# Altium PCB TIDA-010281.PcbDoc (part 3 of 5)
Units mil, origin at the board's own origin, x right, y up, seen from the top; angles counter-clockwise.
Board outline 3455.86 x 1121.8 mil, 8 copper layers (Top Layer, GND1, Sig1, PWR1, PWR2, Sig2, GND2, Bottom Layer), stack 59.155 mil thick; 291 components, 180 nets, 941 pads, 539 vias.
Unrouted connection lines stored in the file: 41.
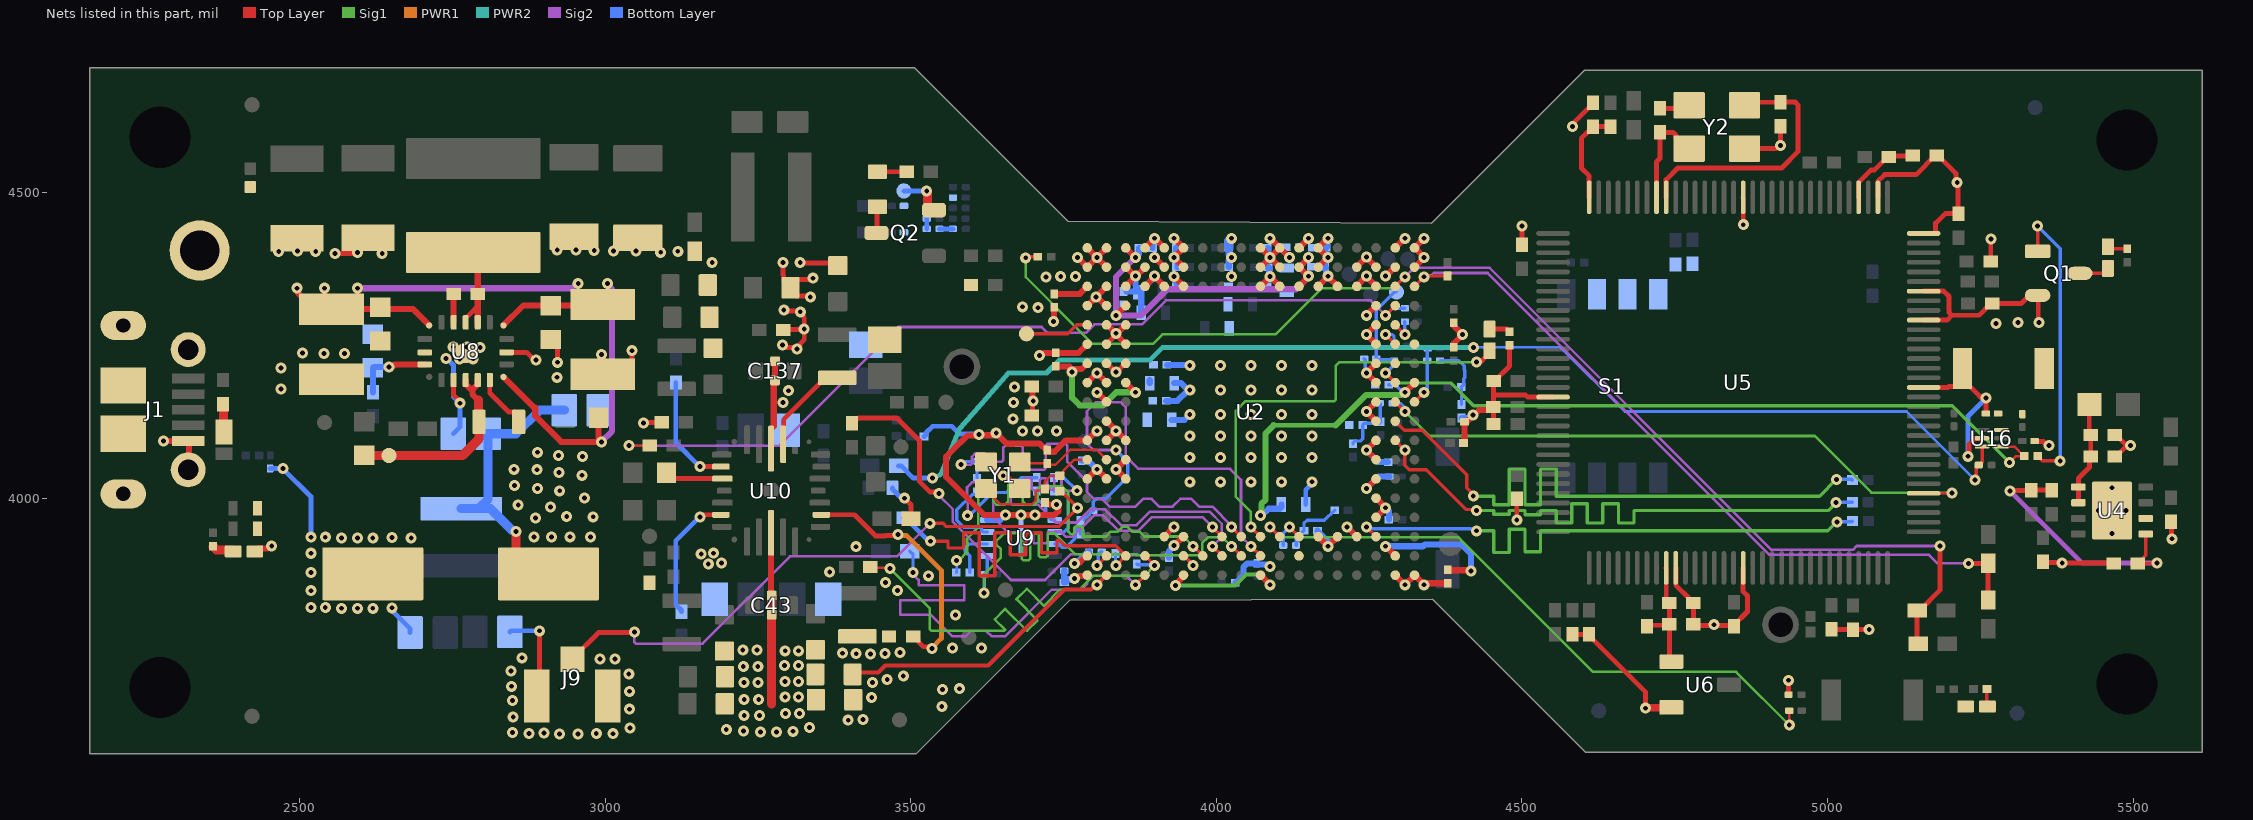
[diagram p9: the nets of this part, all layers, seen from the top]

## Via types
v1: diameter 18, hole 8, Top Layer to Bottom Layer, tented both sides, 533 vias
v2: diameter 19.68, hole 7.87, Top Layer to Bottom Layer, 5 vias
v3: diameter 17, hole 8, Top Layer to Bottom Layer, tented both sides, 1 vias

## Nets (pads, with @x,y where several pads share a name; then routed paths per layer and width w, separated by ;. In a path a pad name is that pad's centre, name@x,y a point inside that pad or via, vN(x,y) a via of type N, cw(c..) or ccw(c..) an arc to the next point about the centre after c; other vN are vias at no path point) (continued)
AR_1V8: C54.2 C55.1 C56.1 C57.1 C58.1 C59.1 C60.1 C61.1 C62.1 C63.1 C64.1 C65.1 C66.1 C67.1 C68.1 C77.2 L7.2 R121.2 U2.A12 U2.B1 U2.C11 U2.C15 U2.C18 U2.F1 U2.K1 U2.M16 U2.M17 U2.M18 U2.U2 U2.V11 | length 2277.4
  Top Layer w7: C54.2@3404.97,3711.44 3408.06,3714.53 3446.79,3714.53 3458.14,3725.89 3626.77,3725.89 3751.24,3850.36 3794.91,3850.36 3802.69,3858.15 v1@3804.51,3858.15 ; C77.2@3405.84,3670.07 C77.2@3406.45,3669.46 ; v1(3804.62,3858.15) v1@3804.51,3858.15 ; U2.B1@3820.26,3873.89 v1@3804.51,3858.15
  Top Layer w10: C63.1@3737.19,4215.47 3759.7,4215.47 3759.7,4212.67 3764,4208.36 v1(3764,4206.2) ; v1@3764,4211.16 3779.58,4211.16 U2.A12@3788.76,4220.35 ; v1(3835.75,4298.83) U2.C15@3851.76,4314.84 ; U2.C11@3851.76,4188.85 v1(3867.5,4173.11) ; U2.C18@3851.76,4409.33 v1(3867.5,4393.58) ; v1(3933.28,3857.12) 3934.81,3858.65 3934.81,3860.9 3946.24,3872.34 U2.F1@3946.24,3873.89 ; U2.K1@4072.23,3873.89 v1(4087.98,3858.15) ; U2.M16@4135.22,4346.33 4135.22,4346.77 4150.97,4362.51 v1(4150.97,4362.94) ; U2.M18@4135.22,4409.33 v1(4150.97,4425.07) ; v1@4150.97,4362.08 U2.M17@4135.22,4377.83 v1(4150.97,4393.58) ; v1(4276.95,3921.14) U2.U2@4292.7,3905.39 ; v1(4308.45,4173.11) U2.V11@4324.2,4188.85 ; C60.1@4378.33,3882.68 4379.19,3881.82 4415.97,3881.82 v1(4416.83,3880.96)
  Sig1 w7: v1(3933.28,3857.12) 4030.72,3857.12 4048.7,3875.1 4071.02,3875.1 v1(4087.98,3858.15)
  Sig1 w8: 4093.73,4119.09 4195.17,4119.09
  Sig1 w10: v1(3764,4206.2) 3764,4163.79 3776.3,4151.49 3814.59,4151.49 3836.2,4173.11 v1(3867.5,4173.11) ; v1(4072.24,3971.63) 4073.78,3973.16 4073.78,3990.32 4080.1,3996.65 4080.1,4105.46 4093.73,4119.09 ; 4195.17,4119.09 4244.54,4168.46 4303.81,4168.46 v1(4308.45,4173.11)
  Sig2 w10: v1@3835.69,4297.67 3836.86,4298.83 3876.84,4298.83 3919.6,4341.59 4130.47,4341.59 4150.97,4362.08 v1(4150.97,4362.94) ; v1(3835.75,4298.83) 3835.75,4361.82 v1(3867.5,4393.58)
  Bottom Layer w5.5: C61.1@4282,4185.3 4292.87,4185.3 4305.07,4173.11 v1(4308.45,4173.11)
  Bottom Layer w10: v1(3867.5,4393.58) 3873.35,4399.42 C68.1@3873.35,4409.24 ; C65.1@3891,4188 C65.1@3891,4192.68 ; v1(4072.24,3971.63) 4074.41,3971.63 4085.36,3982.57 4103.74,3982.57 4106.24,3985.07 C59.1@4106.24,3989.57 ; v1(4276.95,3921.14) 4338.22,3921.14 4341.28,3924.2 4400.39,3924.2 4416.83,3907.76 v1(4416.83,3880.96)
  other v1: 3397.65,3636.55 3421.77,3637.6 3436.12,3673.98 3437.45,3698.29 3461.48,3703.42 3487.69,3708.55 3410.75,3745.31 3434.22,3745.02 3388.24,3746.16 3457.58,3745.69 3482.37,3747.02 3738.48,4109.58
AR_CS1: R9.2 R91.1 U2.C2 | length 735.4
  Top Layer w5.5: v1(3532.57,3929.37) 3560.83,3929.37 3560.83,3918.26 3586.33,3918.26 3586.33,3943.43 3611.83,3943.43 3611.83,3872.77 3637.33,3872.77 3637.33,3943.43 3662.83,3943.43 3662.83,3907.17 3688.33,3907.17 3688.33,3943.43 3713.83,3943.43 3713.83,3910.66 3739.33,3910.66 3739.33,3931.28 3742.55,3931.28 3751.83,3922 3835.15,3922 3849.01,3908.14 U2.C2@3851.76,3905.39 v1(3836.01,3889.64)
  Bottom Layer w5.5: R9.2@3835,3909.17 3835,3890.65 v1(3836.01,3889.64)
  Bottom Layer w8: R91.1@3488.75,3967.81 3490.72,3967.81 3526.77,3931.76 3530.18,3931.76 v1(3532.57,3929.37)
AR_GPIO_0: U2.M2
AR_GPIO_1: R129.2 U2.L3 | length 1033
  Top Layer w4.2: v1(4937.34,3628.68) 4937.39,3628.74 4937.39,3652.02 R129.2@4937.45,3652.08
  Top Layer w5.5: v1(4087.98,3952.63) U2.L3@4103.72,3936.89
  Sig1 w4.2: v1@4091.71,3952.63 v1(4087.98,3952.63) 4104.87,3935.74 4395.79,3935.74 4616.05,3715.47 4850.55,3715.47 v1(4937.34,3628.68)
AR_GPIO_2: LD3.1 U2.K3 | length 713.6
  Top Layer w5.5: v1(4056.48,3952.63) U2.K3@4072.23,3936.89
  Top Layer w8: v1(4425.64,4222.47) 4427.55,4224.38 4434.38,4224.38 4447.13,4237.13 LD3.1@4447.13,4241.07
  Sig1 w4.2: v1(4056.48,3952.63) 4056.48,3977.37 4031.74,4002.11 4031.74,4142.65 4047.18,4158.09 4192.72,4158.09 4195.18,4160.55 4195.18,4216.27 4201.38,4222.47 v1(4425.64,4222.47)
AR_HOSTINTR1: R3.1 U2.B2 | length 48.9
  Top Layer w5.5: v1(3804.51,3889.64) U2.B2@3820.26,3905.39
  Bottom Layer w5.5: v1(3804.51,3889.64) 3806.9,3892.03 3806.9,3906.61 3808.61,3908.31 3808.61,3909.61 3811.22,3912.22 R3.1@3812.51,3912.22
AR_MCUCLKOUT: U2.V13
AR_MISO1: R139.1 U2.D1 | length 768.2
  Top Layer w5.5: v1(3867.5,3858.15) U2.D1@3883.25,3873.89
  Sig2 w4.2: v1(3503.64,3878.26) 3503.64,3875.22 3512.94,3865.92 3512.94,3857.27 3587.52,3857.27 3587.52,3833.07 3482.61,3833.07 3482.61,3808.87 3532.82,3808.87 3534.92,3806.77 3567.99,3773.7 3589.51,3773.7 3598.68,3782.86 3623.39,3782.86 3632.55,3773.7 3654.07,3773.7 3730.65,3850.27 3779.06,3850.27 3788.76,3859.97 3788.76,3863.04 3798.46,3872.75 3852.9,3872.75 v1(3867.5,3858.15)
  Bottom Layer w5.5: R139.1@3498.24,3913.28 3503.64,3907.88 v1(3503.64,3878.26)
AR_MOSI1: R136.2 U2.F2 | length 773.8
  Top Layer w5.5: U2.F2@3946.24,3905.39 3947.09,3905.39 3961.99,3890.49 v1(3961.99,3889.64)
  Top Layer w8: R136.2@3403.94,4122.66 3403.94,4124.63 3409.78,4130.48 3413.78,4130.48 3414.47,4131.16 3476.56,4131.16 3514.37,4093.35 3514.37,4026.92 3531.61,4009.68 3544.25,4009.68 v1(3546.16,4007.77)
  Sig2 w4.2: v1(3546.16,4007.77) 3546.16,4004.42 3568.88,3981.71 3568.88,3960.92 3663.87,3865.92 3719.69,3865.92 3761.57,3907.8 3853.13,3907.8 3854.15,3906.77 3945.71,3906.77 3961.99,3890.49 v1(3961.99,3889.64)
AR_NERR_OUT: R21.1 R94.1 U2.U15 | length 1446.5
  Top Layer w4.2: v1(3039.16,4085.79) 3072.59,4085.79 R94.1@3072.69,4085.88
  Top Layer w5.5: v1(4276.95,4299.09) U2.U15@4292.7,4314.84
  Sig2 w4.2: v1(3039.16,4085.79) 3285.02,4085.79 3479.14,4279.9 3714.18,4279.9 3723.76,4270.31 3786.58,4270.31 3800.5,4284.23 3878.22,4284.23 3917.54,4323.55 4252.49,4323.55 v1(4276.95,4299.09)
  Bottom Layer w5.5: v1(4276.95,4299.09) 4288.62,4310.76 R21.1@4308.45,4310.76
AR_NERRIN: R22.1 U2.U14 | length 43.4
  Top Layer w5.5: U2.U14@4292.7,4283.34 v1(4308.45,4267.59)
  Bottom Layer w5.5: v1(4308.45,4267.59) R22.1@4308.45,4288.76
AR_NRST: C130.1 R59.1 R108.1 TP14.1 U2.U11 U16.4 | length 1353.6
  Top Layer w4.2: U16.4@5284.42,4084.09 5305.57,4084.09 R108.1@5320.98,4068.68 ; v1(5297.5,4058.31) 5298.02,4058.31 5308.38,4068.68 R108.1@5321.77,4068.68
  Top Layer w5.5: v1(4276.95,4204.6) U2.U11@4292.7,4188.85
  Sig1 w5.5: v1(4276.95,4204.6) 4293.2,4188.36 4383.59,4188.36 4420.7,4151.25 5204.3,4151.25 5297.23,4058.31 v1(5297.5,4058.31)
  Bottom Layer w5.5: v1(4276.95,4204.6) 4289.15,4216.8 4289.15,4224.04 4286.81,4226.38 4263.32,4226.38 C130.1@4261.7,4228 4261.3,4228.4 4261.3,4307.3 4291.1,4337.1 TP14.1@4294.6,4337.1
AR_NRST_2: C120.1 R124.1 SW2.1 U16.6
AR_NRST_PMIC: R95.1 R178.2 U16.3 | length 2030.1
  Top Layer w5.5: v1(5241.09,4029.84) 5243.48,4032.23 5243.48,4051.48 5246.09,4054.09 R178.2@5247.38,4054.09 5248.68,4054.09 5252.92,4058.33 U16.3@5252.92,4084.09
  PWR2 w8: v1@3535.23,4032.51 v1(3535.48,4032.61) 3548.12,4037.85 3549.31,4039.03 3550.58,4042.11 3580.42,4114.08 3580.68,4114.72 3581.12,4115.23 ; 3581.16,4115.27 3659.92,4204.66 3722.02,4204.66 3743.11,4225.76 3891.12,4225.76 3912,4246.64 v1(4420.77,4246.64)
  Bottom Layer w4.2: v1(4420.77,4246.64) 4563.37,4246.64 4668.4,4141.61 5129.32,4141.61 v1(5241.09,4029.84)
  Bottom Layer w8: R95.1@3480.19,4052.72 3484.13,4052.72 3504.23,4032.61 v1(3535.48,4032.61)
AR_OSC_CLKOUT: TP17.1 U2.A14 | length 105.5
  Top Layer w5.5: TP17.1@3689.3,4268.85 3756.96,4268.85 3771.45,4283.34 U2.A14@3788.76,4283.34
AR_PMIC_CLKOUT_SOP2: R85.1 R103.1 U2.V10 | length 96.6
  Top Layer w5.5: U2.V10@4324.2,4157.36 v1(4339.94,4173.11)
  Bottom Layer w5.5: v1(4339.94,4173.11) 4344.93,4178.09 R85.1@4344.93,4224.99 4344.93,4244.41 R103.1@4345.62,4245.1
AR_QSPI_CLK: R47.1 U2.H2 | length 760.7
  Top Layer w5.5: v1(3993.49,3921.14) U2.H2@4009.24,3905.39
  Sig2 w4.2: v1(3772.05,4012.05) 3750.13,4012.05 3746.55,4015.63 3746.55,4029.87 3744.09,4032.33 3737.42,4032.33 3734.96,4029.87 3734.96,4016.39 3732.5,4013.93 3729.02,4013.93 3723.42,4019.53 3723.42,4029.87 3720.96,4032.33 3714.18,4032.33 3711.36,4029.52 3711.36,4015.63 3708.59,4012.85 3700.3,4012.85 3697.84,4015.31 3697.84,4029.87 3695.38,4032.33 3687.98,4032.33 3685.52,4029.87 3685.52,4015.31 3683.06,4012.85 3678.7,4012.85 3676.24,4015.31 3676.24,4027.38 3673.78,4029.84 3667.82,4029.84 3663.86,4025.88 3663.86,3991.69 3666.33,3989.23 3708.08,3989.23 3737.31,3960 3771.94,3960 3793.6,3981.66 3817.72,3981.66 3843.6,3955.77 3869.39,3955.77 3891.32,3977.7 3989.07,3977.7 4008.79,3957.98 4008.79,3936.82 4008.98,3936.63 v1(3993.49,3921.14)
  Bottom Layer w5.5: R47.1@3734.37,4033.51 3750.59,4033.51 v1(3772.05,4012.05)
AR_QSPI_CLK_T: R47.2 U9.6 | length 102.2
  Bottom Layer w5.5: R47.2@3734.37,4011.47 3747.4,4011.47 3757.25,4001.62 3757.25,3950.78 3750.99,3944.52 U9.6@3735.4,3944.52
AR_QSPI_CS: R43.1 U2.J2 U9.1 | length 770.9
  Top Layer w5.5: v1(4024.98,3921.14) U2.J2@4040.73,3905.39
  Sig1 w4.2: v1(3619.9,3844.47) 3619.9,3875.21 3647.47,3902.79 3647.47,3916.63 3639.73,3924.37 3639.73,3929.34 3647.76,3937.38 3652.78,3942.4 3652.87,3942.4 3667.07,3942.4 3678.43,3942.4 3681.27,3939.56 3681.27,3900.87 3684.11,3898.03 3692.63,3898.03 3695.47,3900.87 3695.47,3939.56 3698.31,3942.4 3706.83,3942.4 3709.67,3939.56 3709.67,3905.77 3712.51,3902.93 3721.03,3902.93 3723.87,3905.77 3723.87,3939.56 3726.71,3942.4 3730.97,3942.4 3735.14,3942.4 3769.74,3907.8 3869.64,3907.8 3870.91,3906.54 3970.81,3906.54 3976.59,3912.32 3976.59,3926.37 3985.96,3935.74 4010.38,3935.74 v1(4024.98,3921.14)
  Bottom Layer w5.5: v1(3619.9,3844.47) 3620.04,3844.61 3620.04,3873.99 3624.09,3878.04 3624.09,3880.18 3625.17,3881.26 U9.1@3625.17,3905.15
AR_QSPI_D0: R6.1 U2.H3 | length 745.1
  Top Layer w5.5: v1(3993.49,3952.63) U2.H3@4009.24,3936.89
  Sig2 w4.2: v1(3593.03,3971.08) 3593.03,3997.08 3592.02,3998.09 3592.02,4017.53 3600.13,4025.64 3615.59,4025.64 3635.24,4005.99 3635.24,3967.78 3659.02,3944 3697.84,3944 3700.3,3941.54 3700.3,3928.47 3702.76,3926.01 3721.3,3926.01 3723.76,3928.47 3723.76,3942.64 3726.22,3945.1 3745.36,3945.1 3753.84,3936.63 3764.21,3936.63 3799.43,3971.85 3814.73,3971.85 3839.99,3946.58 3872.3,3946.58 3894.55,3968.83 3977.29,3968.83 v1(3993.49,3952.63)
  Bottom Layer w5.5: v1(3593.03,3971.08) 3595.33,3971.08 3633.25,4009 3656,4009 3680.51,4033.51 R6.1@3706.27,4033.51
AR_QSPI_D0_T: R6.2 U9.5 | length 62.4
  Bottom Layer w5.5: R6.2@3706.27,4011.47 3706.27,3999.75 3720.96,3985.06 3720.96,3973.39 3730.15,3964.2 U9.5@3735.4,3964.2
AR_QSPI_D1: R46.1 U2.G2 | length 750.6
  Top Layer w5.5: v1(3961.99,3921.14) U2.G2@3977.74,3905.39
  Sig1 w4.2: v1(3575.01,3898.14) 3578.74,3898.14 3592,3911.39 3592,3933.42 3610.05,3951.47 3610.05,4005.15 3624.12,4019.22 3630.16,4019.22 3635,4014.38 3635,3994.04 3639.84,3989.2 3654.36,3989.2 3659.2,3994.04 3659.2,4019.22 3659.2,4021.32 3664.04,4026.16 3678.56,4026.16 3683.4,4021.32 3683.4,4019.22 3683.4,3994.04 3688.24,3989.2 3702.76,3989.2 3707.6,3994.04 3707.6,4014.38 3712.44,4019.22 3719.7,4019.22 3747.78,4019.22 3757.72,4009.29 3757.72,3944.96 3761.68,3941 3765.15,3941 3767.62,3943.46 3767.62,3951.66 3770.08,3954.12 3778.7,3954.12 3781.16,3951.66 3781.16,3937.16 3819.13,3937.16 3826.93,3944.97 3838.83,3944.97 3846.75,3952.89 3854.7,3952.89 3862.62,3944.97 3874.51,3944.97 3882.32,3937.16 3945.97,3937.16 v1(3961.99,3921.14)
  Bottom Layer w4.2: R46.1@3574.6,3878.26 3575.01,3878.67 v1(3575.01,3898.14)
AR_QSPI_D1_T: R46.2 U9.2 | length 83.1
  Bottom Layer w5.5: R46.2@3596.64,3878.26 3596.64,3905.95 3593.42,3909.17 3592.42,3909.17 3589.2,3912.4 3589.2,3919.54 3594.49,3924.83 U9.2@3625.17,3924.83
AR_QSPI_D2: R44.1 R48.1 U2.J3 | length 744.4
  Top Layer w5.5: v1(4024.98,3952.63) U2.J3@4040.73,3936.89
  Sig2 w4.2: v1(3582.3,4054.72) 3582.8,4054.22 3597.67,4054.22 3600.13,4056.68 3600.13,4067.62 3606.02,4073.51 3619.64,4073.51 3633.55,4059.59 3648.9,4059.59 3651.36,4062.05 3651.36,4082.68 3654.68,4086 3680.37,4086 3683.06,4083.31 3683.06,4049.04 3685.52,4046.58 3718.5,4046.58 3720.96,4049.04 3720.96,4086.38 3723.42,4088.84 3752.99,4088.84 3755.83,4086 3755.83,4059.59 3788.32,4027.1 3788.32,4010.18 3799.77,3998.73 3812.87,3998.73 3825.5,3986.1 3867.51,3986.1 3880.14,3998.73 3893.84,3998.73 3906.47,3986.1 3928.24,3986.1 3940.87,3998.73 3959.14,3998.73 3971.77,3986.1 3993.54,3986.1 4024.98,3954.65 v1(4024.98,3952.63)
  Bottom Layer w5.5: v1(3582.3,4054.72) 3585.68,4054.72 3590.81,4059.85 R44.1@3608.37,4059.85 ; R48.1@3608.37,4032.12 R44.1@3608.37,4059.85 ; R44.1@3608.85,4059.85 R44.1@3608.37,4059.85
AR_QSPI_D2_T: R48.2 U9.3 | length 121.9
  Bottom Layer w5.5: R48.2@3608.37,4010.07 3608.37,4009.28 3604.82,4005.73 3600.39,4005.73 3575.38,3980.72 3575.38,3963.77 3586.62,3952.53 3612.88,3952.53 3616.11,3949.31 3616.11,3946.69 3618.28,3944.52 U9.3@3625.17,3944.52
AR_QSPI_D3: R45.1 R49.1 U2.K2 | length 763.2
  Top Layer w5.5: v1(4056.48,3921.14) U2.K2@4072.23,3905.39
  Sig2 w4.2: v1(3836.01,4078.62) 3798.6,4078.62 3788.37,4088.84 3788.37,4142.05 3803.23,4156.91 3843.24,4156.91 3851.54,4148.61 3851.54,4069 3872.83,4047.7 4022.42,4047.7 4040.28,4029.84 4040.28,3937.33 v1(4056.48,3921.14)
  Bottom Layer w4.2: R49.1@3782.81,3963.66 3782.81,3964.44 3787.01,3968.64 3787.79,3968.64 3794.14,3974.99 3794.14,3975.65 3797.41,3978.91 R45.1@3798.7,3978.91
  Bottom Layer w5.5: R45.1@3798.7,3978.91 3798.7,3993.8 3803.85,3998.95 3819.33,3998.95 3855.08,4034.7 3855.08,4059.54 v1(3836.01,4078.62)
AR_QSPI_D3_T: R49.2 U9.7 | length 71.2
  Bottom Layer w5.5: U9.7@3735.4,3924.83 3742.29,3924.83 3744.46,3922.66 3744.46,3922.04 3746.97,3919.54 3754.14,3919.54 3764.67,3930.07 3765.07,3930.07 3768.4,3933.39 3768.4,3945.8 3771.62,3949.03 3776.18,3949.03 3776.18,3945.49 3777.55,3944.11 R49.2@3777.55,3941.21
AR_RS232RX: R5.2 R30.2 R63.1 U2.V16 | length 1246.3
  Top Layer w5.5: U2.V16@4324.2,4346.33 v1(4339.94,4362.08) 4341.11,4363.24 R5.2@4378.13,4363.24
  Top Layer w8: v1(5230.62,3893.11) 5262.54,3893.11 R63.1@5262.71,3893.28 R30.2@5262.71,3833.28
  Sig1 w4.2: v1(4339.94,4362.08) v1@4343.11,4362.08
  Sig2 w4.2: v1(4339.94,4362.08) 4342.59,4364.72 4352.28,4364.72 4355.84,4368.28 4443.77,4368.28 4905.07,3906.98 5166.19,3906.98 5180.07,3893.11 v1(5230.62,3893.11)
AR_RS232TX: R4.2 R38.2 R51.1 U2.U16 | length 2038.2
  Top Layer w5.5: v1@3688.09,4394.61 R4.2@3707.72,4394.61 R4.2@3707.9,4394.43 ; U2.U16@4292.7,4346.33 v1(4308.45,4362.08)
  Top Layer w8: R38.2@5148.39,3761.87 5146.6,3763.66 R51.1@5146.6,3816.05 5150.54,3816.05 5184.16,3849.68 v1(5184.16,3921.54)
  Sig1 w4.2: v1(3688.09,4393.11) 3688.09,4361.33 3796.59,4252.83 3896.89,4252.83 3911.84,4267.77 4097,4267.77 4172.61,4343.38 4289.75,4343.38 v1(4308.45,4362.08)
  Sig2 w4.2: v1(4308.45,4362.08) 4323.05,4376.68 4447.25,4376.68 4908.55,3915.38 5041.41,3915.38 5047.57,3921.54 v1(5184.16,3921.54)
AR_SOP0: R83.2 R158.2 R159.1 R174.2 | length 105.5
  Bottom Layer w5.5: R159.1@4223.5,4089.12 4223.5,4089.91 4227.05,4093.46 4236,4093.46 4239.22,4096.68 R158.2@4239.22,4119.6 4241.84,4122.21 4266.49,4122.21 R174.2@4269.1,4124.82 4268.19,4125.73 4268.19,4154.39 R83.2@4267.28,4155.3
AR_SOP1: R84.2 R170.2 R171.1 | length 100.6
  Bottom Layer w5.5: R84.2@4130.41,3922.4 4130.41,3933.54 R170.2@4143.32,3946.46 4143.32,3958.65 4148.32,3963.64 4176.89,3963.64 R171.1@4193.42,3980.18
AR_SOP2: R85.2 R172.2 R176.2 | length 109.7
  Bottom Layer w5.5: R85.2@4365.96,4224.99 4396.89,4224.99 4405.74,4216.14 4405.74,4209.91 4406.2,4209.44 4406.2,4196.48 4404.96,4195.24 4404.96,4185.35 4401.41,4181.8 R176.2@4400.62,4181.8 4401.11,4181.32 R172.2@4401.11,4153.05
AR_SPICLK1: R75.2 R134.2 U2.D2 | length 780.8
  Top Layer w4.2: R134.2@3435.11,3886.26 v1@3464.75,3886.26
  Top Layer w5.5: U2.D2@3883.25,3905.39 v1(3899,3889.64)
  Top Layer w8: R134.2@3433.89,3887.48 R134.2@3435.11,3886.26 ; v1@3464.75,3886.26 v1(3465.97,3885.04)
  Sig1 w4.2: v1(3465.97,3885.04) 3531.37,3819.64 3531.37,3785.32 3533.83,3782.86 3649.46,3782.86 3652.43,3782.86 3654.17,3784.6 3637.38,3801.39 3654.5,3818.5 3690.1,3782.9 3707.21,3800.01 3672.69,3834.53 3689.8,3851.65 3717.83,3823.61 3744.5,3850.27 3775.99,3850.27 3798.46,3872.75 3882.1,3872.75 v1(3899,3889.64)
  Bottom Layer w5.5: R75.2@3869.6,3892.2 3870.88,3890.92 3897.72,3890.92 v1(3899,3889.64)
AR_SYNC_IN: U2.U12
AR_SYNC_OUT_SOP1: R84.1 U2.M3 | length 56.7
  Top Layer w5.5: v1(4119.47,3952.63) U2.M3@4135.22,3936.89
  Bottom Layer w5.5: R84.1@4109.37,3922.4 4109.37,3942.53 v1(4119.47,3952.63)
AR_TCK: R66.2 U2.T3 | length 971.9
  Top Layer w5.5: v1(4245.46,3952.63) U2.T3@4261.2,3936.89
  Sig1 w5.5: v1(4425.64,3946.46) 4453.89,3946.46 4453.89,3910.92 4479.39,3910.92 4479.39,3949.1 4504.89,3949.1 4504.89,3912.07 4530.39,3912.07 4530.39,3946.46 4720.7,3946.46 5000.64,3946.46 v1(5015.19,3961.01)
  Bottom Layer w5.5: v1(4245.46,3952.63) 4247.85,3950.24 4254.61,3950.24 4254.93,3949.93 4416.17,3949.93 4417.24,3948.85 4423.25,3948.85 v1(4425.64,3946.46) ; v1(5015.19,3961.01) 5039.65,3961.01 R66.2@5040.83,3962.19
AR_TDI: R69.2 U2.U9 | length 1057.3
  Top Layer w5.5: U2.U9@4292.7,4125.86 4307.77,4110.79 4336.9,4110.79 4409.76,4037.94 4409.76,4017.04 4420.37,4006.43 v1(4420.37,4003.26)
  Sig1 w5.5: v1(4420.37,4003.26) 4420.62,4003 4425.64,4003 4453.89,4003 4453.89,3989.3 4479.39,3989.3 4479.39,4047.46 4504.89,4047.46 4504.89,3989.3 4530.39,3989.3 4530.39,4047.46 4555.89,4047.46 4555.89,4003 4582.9,4003 4986.91,4003 v1(5014.42,4030.51)
  Bottom Layer w5.5: v1(5014.42,4030.51) 5039.41,4030.51 R69.2@5040.49,4029.42
AR_TDO_SOP0: R83.1 U2.U10 U5.37 | length 1048.9
  Top Layer w4.2: U5.37@5157.18,4007.77 5157.33,4007.91 5203.63,4007.91 v1(5203.78,4008.06)
  Top Layer w5.5: U2.U10@4292.7,4157.36 v1(4308.45,4141.61)
  Sig1 w4.2: v1(4308.45,4141.61) 4348.46,4101.59 4979.27,4101.59 5071.83,4009.04 v1@5203.78,4009.04
  Bottom Layer w4.2: R83.1@4288.32,4155.3 4301.27,4155.3 4308.45,4148.13 v1(4308.45,4141.61)
AR_TMS: R67.2 U2.U8 | length 1007.7
  Top Layer w5.5: U2.U8@4292.7,4094.37 v1(4308.45,4078.62) 4308.45,4053.32 4315.63,4046.14 4343.65,4046.14 4408.39,3981.4 4423.84,3981.4 v1(4425.64,3979.6)
  Sig1 w5.5: v1(4425.64,3979.6) 4453.89,3979.6 4453.89,3973.78 4479.39,3973.78 4479.39,3979.6 4504.89,3979.6 4504.89,3972.55 4530.39,3972.55 4530.39,3979.6 4555.89,3979.6 4555.89,3959.2 4581.39,3959.2 4581.39,3990.56 4606.89,3990.56 4606.89,3959.2 4632.39,3959.2 4632.39,3990.56 4657.89,3990.56 4657.89,3959.2 4683.39,3959.2 4683.39,3979.6 4692.04,3979.6 5000.74,3979.6 v1(5014.06,3992.92)
  Bottom Layer w5.5: v1(5014.06,3992.92) 5040.28,3992.92 R67.2@5040.51,3993.15
AR_VBGAP: C69.1 U2.A16 | length 59.2
  Top Layer w10: C69.1@3734.67,4334 3776.43,4334 U2.A16@3788.76,4346.33
AR_WARMRST: R23.1 U2.U13 | length 52.5
  Top Layer w5.5: v1(4276.95,4267.59) U2.U13@4292.7,4251.85
  Bottom Layer w5.5: v1(4276.95,4267.59) 4287.51,4267.59 4290.72,4264.38 R23.1@4290.72,4249.29
AR_XTAL_N: C71.2 U2.B7 Y1.3 | length 159.9
  Top Layer w4: Y1.3@3678.09,4056.69 3720.4,4056.69 3722.86,4054.22 3736.32,4054.22 3760.84,4078.74 3804.39,4078.74 U2.B7@3820.26,4062.87
AR_XTAL_P: C14.2 R109.1 U2.A7 Y1.1 | length 226
  Top Layer w4: Y1.1@3621.87,4014.49 3646.72,3989.63 3697.93,3989.63 3704.65,3996.36 3704.65,4009.85 3707.19,4012.38 3719.34,4012.38 3719.34,4027.12 3728.93,4036.7 3744.81,4036.7 3749.7,4041.59 3749.7,4044.95 3767.62,4062.87 U2.A7@3788.76,4062.87
BOOTN: R80.2 R96.1 | length 21.7
  Bottom Layer w8: R96.1@3547.14,4440.29 R80.2@3568.85,4440.29
BUCK_VCC: C116.1 R113.1 TP4.1 U8.4 U8.5 | length 324.4
  Top Layer w10: U8.4@2771.82,4193.15 2771.82,4186.26 2782.68,4175.39 ; U8.5@2791.5,4193.15 2791.5,4186.26 2782.68,4177.44 2782.68,4175.39 ; 2792.55,4160.23 2782.68,4170.1 2782.68,4175.39
  Top Layer w15: R113.1@2605.99,4069.91 2606.24,4069.66 TP4.1@2646.13,4069.66 2766.6,4069.66 2793.47,4096.54 C116.1@2793.47,4124.7 ; C116.1@2792.55,4125.63 2792.55,4160.23
BUCK_VIN: C119.2 C122.1 C123.1 C124.1 C125.1 C128.2 C129.2 L1.2 R114.1 U8.7 U8.11 U8.17 | length 1864
  Top Layer w10: v1(2495.65,4343.33) 2497.18,4341.8 2497.18,4335.86 2524.3,4308.74 C124.1@2551.86,4308.74 ; v1(2540.97,4343.33) 2540.97,4319.63 C124.1@2551.86,4308.74 ; v1(2595,4343.33) 2595,4329.33 C124.1@2575.04,4309.37 ; U8.17@2712.02,4282.47 2685.12,4309.37 C124.1@2575.04,4309.37 ; U8.7@2833.58,4198.31 2884.19,4147.7 2885.63,4147.7 2885.63,4134.42 2928.11,4091.95 v1(2993.92,4091.95) 2993.92,4094.11 2989.22,4098.81 R114.1@2989.22,4131.16 ; U8.11@2833.58,4282.47 2866.36,4315.25 2994.67,4315.25 C125.1@2996.02,4316.6 ; C124.1@2551.86,4308.74 2574.41,4308.74 C124.1@2575.04,4309.37
  Top Layer w15: v1(2853.96,3945.1) 2853.96,3915.37 2893.26,3876.06 C129.2@2907.19,3876.06
  Sig2 w10: v1(2595,4343.33) 2946.13,4343.33 2953.68,4350.88 v1(2955.85,4350.88) ; v1(2993.92,4091.95) 3011.42,4109.45 3011.42,4341.57 3003.96,4349.03 v1(3003.96,4351.19)
  Bottom Layer w15: L1.2@2764.49,3982.86 L1.2@2793.24,3982.86 ; v1(2853.96,3945.1) 2852.04,3947.02 2847.97,3947.02 2812.13,3982.86 L1.2@2793.24,3982.86 ; C119.2@2933.08,4143.96 2892.72,4143.96 2853.96,4105.2 C128.2@2808.53,4105.2 2808.53,3998.15 L1.2@2793.24,3982.86
  other v1: 2883.35,3936.38 2911.89,3936.37 2975.99,3936.1 2942.2,3936.64 2885.91,3967.5 2980.4,3969.36 2937.07,3969.59 2910.79,3985.51 2857.71,3988.39 2965.92,4000.1 2925.6,4011.91 2889.29,4015.81 2851.64,4020.34 2961.8,4037.31 2924.27,4041.98 2888.4,4046.33 2850.93,4047.11 2963.03,4068.05 2923.93,4069.39 2889.07,4074.95
CLKSEL0: R82.2
FB_B1: R121.1 U10.3 | length 410.8
  Top Layer w8: U10.3@3353.74,3972.67 3407.88,3972.67 3442.33,3938.22 3458.28,3938.22 3458.5,3938.44 3477.21,3938.44 v1(3479.12,3940.35) ; R121.1@3503.72,3773.64 3505.69,3773.64 3511.53,3767.79 3511.53,3765.82 3520.68,3756.67 3529.17,3756.67 3532.22,3753.62 v1(3534.93,3753.62)
  PWR1 w8: v1(3479.12,3940.35) 3481.03,3938.44 3493.32,3938.44 3550.12,3881.64 3550.12,3770.39 3534.93,3755.2 v1(3534.93,3753.62)
FB_B2: R126.1 U10.21 | length 211.4
  Top Layer w8: v1(3155.05,3968.73) 3157.76,3968.73 3161.7,3972.67 U10.21@3189.37,3972.67
  Bottom Layer w8: R126.1@3124.79,3814.26 3124.79,3816.23 3115.49,3825.53 3115.49,3930.4 3153.81,3968.73 v1(3155.05,3968.73)
FB_B3: R128.1 U10.17 | length 188.4
  Top Layer w8: v1(3154.97,4051.38) U10.17@3189.37,4051.41
  Bottom Layer w8: R128.1@3115.49,4189.05 3115.49,4090.87 v1(3154.97,4051.38)
GND: C1.1 C4.2 C5.2 C6.2 C7.1 C8.1 C9.2 C10.1 C11.2 C12.2 C13.1 C14.1 C16.1 C17.1 C18.1 C19.1 C20.2 C21.2 C22.1 C23.1 C24.1 C25.1 C26.1 C27.1 C28.1 C29.1 C35.1 C36.2 C37.2 C38.2 C39.2 C40.2 C41.2 C42.2 C43.2 C54.1 C55.2 C56.2 C57.2 C58.2 C59.2 C60.2 C61.2 C62.2 C63.2 C64.2 C65.2 C66.2 C67.2 C68.2 C69.2 C70.2 C71.1 C72.1 C73.2 C74.2 C75.2 C76.2 C77.1 C78.2 C79.2 C80.2 C81.2 C82.2 C83.2 C84.2 C85.2 C86.1 C87.2 C88.2 C89.2 C90.2 C91.2 C92.2 C93.1 C94.2 C95.2 C96.2 C97.2 C98.2 C99.1 C100.2 C101.2 C102.2 C103.2 C104.1 C105.1 C106.2 C107.2 C116.2 C118.1 C119.1 C120.2 C122.2 C123.2 C124.2 C125.2 C127.1 C128.1 C129.1 C130.2 C131.2 C132.1 C133.1 C134.1 C135.2 C136.2 C137.2 J1.5 J1.6 J1.7 J1.8 J1.9 J1.10 J1.11 J9.2@3004.32,3676.11 J9.3@2888.18,3676.11 LD1.2 LD2.2 NT1.2 NT2.2 NT3.2 NT4.1 Q1.2 Q2.2 R3.2 R24.1 R27.1 R29.1 R42.2 R65.1 R72.2 R73.2 R90.1 R93.2 R96.2 R97.1 R98.2 R112.1 R119.1 R122.2 R125.1 R131.1 R141.2 R158.1 R170.1 R172.1 S1.6 S1.7 S1.8 SW2.2 TP15.1 TP20.1 U2.A1 U2.A2 U2.A6 U2.A8 U2.A11 U2.A13 U2.A15 U2.A17 U2.A18 U2.B6 U2.B8 U2.B9 U2.B10 U2.B11 U2.B12 U2.B13 U2.B14 U2.B15 U2.B16 U2.B17 U2.B18 U2.C6 U2.C7 U2.C8 U2.C12 U2.C13 U2.C14 U2.C16 U2.C17 U2.D16 U2.D17 U2.D18 U2.E3 U2.E16 U2.E17 U2.E18 U2.F3 U2.F16 U2.F17 U2.F18 U2.K16 U2.K17 U2.K18 U2.L16 U2.L17 U2.L18 U2.N3 U2.N16 U2.N17 U2.N18 U2.P3 U2.P16 U2.R3 U2.R16 U2.R17 U2.T4 U2.T5 U2.T6 U2.T7 U2.T8 U2.T9 U2.T10 U2.T11 U2.T12 U2.T13 U2.T14 U2.T15 U2.T16 U2.T17 U2.U1 U2.U17 U2.U18 U2.V1 U2.V17 U2.V18 U4.6 U4.9@5465.42,3979.58 U5.10 U5.17 U5.48 U5.55 U5.58 U5.64 U5.66 U5.80 U5.114 U6.2 U8.3 U8.6 U8.9 U8.19 U8.21 U9.4 U9.9 U10.12 U10.26 U16.2 Y1.2 Y1.4 Y2.2 Y2.4 | length 8245.1
  Top Layer w8: v1(2558.23,4400.16) 2558.31,4400.24 v1@2593.3,4400.24 ; v1(2595,4401.99) 2595,4408.91 C131.2@2611.98,4425.89 ; U8.3@2752.13,4193.15 2752.13,4168.15 2762.37,4157.91 v1(2762.37,4155.21) ; U8.6@2811.19,4193.15 2811.19,4171.95 2842.62,4140.51 2851.48,4140.51 2858.43,4133.56 C116.2@2858.43,4124.7 ; U8.9@2838.75,4238.42 2871.71,4238.42 2884.4,4225.74 v1(2887.11,4225.74) ; J9.3@2888.18,3676.11 2892.72,3680.64 v1(2892.72,3782.86) ; C122.2@2910.99,4259.46 2922,4248.45 v1(2922,4222.13) ; C125.2@2996.02,4202.43 3023.58,4202.43 3043.92,4222.77 v1(3043.92,4241.04) ; v1(3062.58,4122.88) 3063.15,4123.45 3091.8,4123.45 R122.2@3092.37,4124.03 ; v1(3290.29,4250.59) 3292.99,4250.59 3297.51,4246.07 3311.79,4246.07 v1(3313.71,4244.16) ; C37.2@3291.24,4274.8 3292.2,4275.76 3324.73,4275.76 v1(3325.69,4276.72) ; v1(3291.24,4385.51) 3291.24,4364.51 3292.11,4363.64 3292.11,4355.08 C27.1@3302.88,4344.32 ; v1(3292.16,4307.72) 3293.61,4306.27 3317.71,4306.27 v1(3319.16,4304.82) 3319.16,4302.12 3325.69,4295.58 v1(3325.69,4276.72) ; v1@3312.24,4245.62 3316.45,4249.83 3319.16,4249.83 3319.16,4252.54 3325.69,4259.07 v1(3325.69,4276.72) ; v1(3319.15,4385.52) 3320.14,4384.53 3376.46,4384.53 C105.1@3380.58,4380.41 ; v1(3335.53,4329.19) 3333.87,4330.86 3313.64,4330.86 3302.88,4341.62 C27.1@3302.88,4344.32 ; v1(3339.74,4359.69) 3337.96,4357.9 3313.64,4357.9 3302.88,4347.14 C27.1@3302.88,4344.32 ; v1(3489.9,3999.72) 3500.3,3989.32 R141.2@3500.3,3966.37 ; C89.2@3697.82,4135.45 3699.06,4136.69 3699.06,4157.52 v1(3700.3,4158.76) ; U2.B16@3819.62,4346.33 U2.B16@3820.26,4346.33 ; U2.B12@3820.26,4220.35 3820.97,4220.35 3835.33,4205.99 v1(3836.04,4205.99) 3836.72,4205.99 3851.08,4220.35 U2.C12@3851.76,4220.35 ; U2.B13@3820.26,4251.85 v1@3836.01,4267.59 ; C17.1@4453.44,4120.8 4453.37,4120.87 4453.37,4148.84 C18.1@4453.3,4148.91 4453.51,4149.11 4453.51,4170.36 ; R42.2@4479.55,4250.1 4479.55,4215.67 4455.69,4191.81 C12.2@4453.72,4191.81 4453.51,4191.6 4453.51,4170.36 ; v1(4491.53,3964.35) C10.1@4491.53,3998.9 ; C9.2@4499.97,4414.78 v1(4499.97,4444.91) ; U5.114@4550.88,4165.25 4509.3,4165.25 4506.05,4168.5 4455.37,4168.5 4453.51,4170.36 ; C16.1@4582.9,3776.98 R29.1@4609.94,3776.98 4609.94,3775.01 4701.87,3683.08 v1(4701.87,3656.11) ; v1(4582.9,4608.2) 4584.81,4610.11 4584.81,4613.78 4616.07,4645.04 C21.2@4616.07,4647.01 ; C23.1@4725.84,4637.64 4768.53,4637.64 Y2.2@4773.53,4642.64 ; U5.10@4751.67,3885.72 U5.10@4751.67,3885.72 4751.73,3857.51 4772.78,3836.47 4772.78,3834.5 4778.62,3828.66 C25.1@4780.59,3828.66 C26.1@4780.59,3793.56 4782.39,3791.77 4846.42,3791.77 4869.01,3814.36 4869.01,3839.88 4861.91,3846.99 U5.17@4861.91,3885.72 ; U5.80@4861.91,4492.02 4861.97,4491.96 4861.97,4447.31 v1(4862.09,4447.19) ; Y2.4@4864.08,4571.77 4915.42,4571.77 4920.35,4576.7 v1(4923.05,4576.7) C24.1@4923.05,4608.2 ; R125.1@4936.23,3678.43 v1(4936.22,3701.86) ; C11.2@5006.67,3785.02 5006.76,3784.93 5041.69,3784.93 C7.1@5041.78,3784.84 5041.89,3784.96 5068.03,3784.96 v1(5068.15,3785.07) ; U5.66@5082.38,4492.02 5082.38,4518.04 5093.46,4529.13 5144.91,4529.13 5176.45,4560.66 C22.1@5178.42,4560.66 5180.38,4560.66 5210.26,4530.78 5210.26,4518.13 v1(5212.18,4516.21) 5213.27,4515.12 5213.27,4466.59 R72.2@5214.37,4465.5 5192.52,4465.5 5176.8,4449.78 5176.8,4433.03 5176.74,4432.97 U5.64@5157.18,4432.97 ; U5.48@5157.18,4181 5196.74,4181 5198.23,4182.49 5209.08,4182.49 SW2.2@5220.82,4194.23 ; U5.55@5157.18,4291.23 5195.62,4291.23 5203.48,4299.09 ; U5.58@5157.18,4338.48 5190.04,4338.48 5198.79,4329.73 5198.79,4303.78 5203.48,4299.09 ; SW2.2@5220.82,4211.95 SW2.2@5220.82,4194.23 ; v1(5229.76,4068.4) 5231.67,4070.31 5231.67,4088.16 5240.73,4097.22 5252.26,4097.22 U16.2@5252.92,4097.87 ; C120.2@5259.13,4138.45 v1(5259.14,4163.53) ; v1(5259.14,4163.53) 5257.23,4165.44 5249.62,4165.44 SW2.2@5220.82,4194.23 ; R73.2@5266.71,4387.04 5266.93,4387.27 5266.93,4423.93 v1(5267.16,4424.16) ; C72.1@5338.68,4093.48 5339.85,4092.31 5353.17,4092.31 5359.48,4086 v1(5362.18,4086) ; v1(5345.91,4287.08) 5344.78,4288.2 5344.78,4330.56 Q1.2@5343.65,4331.68 5329.92,4331.68 5316.57,4318.34 R90.1@5269.13,4318.34 5267.16,4318.34 5247.91,4299.09 5203.48,4299.09 ; C13.1@5352.54,3895.84 5353.54,3894.83 5382.9,3894.83 v1(5383.9,3893.83) 5384.18,3893.56 5468.09,3893.56 R27.1@5468.37,3893.28 ; C6.2@5469.63,4103.44 5471.6,4103.44 v1@5487.05,4087.99 ; C5.2@5469.95,4068.12 5471.92,4068.12 5487.96,4084.16 5493.68,4084.16 v1(5495.59,4086.08) ; R24.1@5562.22,3961.39 5562.91,3960.7 5562.91,3934.05 v1(5563.61,3933.36)
  Top Layer w10: v1(2277.16,4093.48) 2277.22,4093.42 2319.31,4093.42 2319.37,4093.35 J1.10@2319.37,4046.11 ; LD1.2@2426.74,3912.62 2431.59,3917.46 2447.81,3917.46 2452.21,3921.86 v1(2454.37,3921.86) ; U10.26@3271.56,3943.14 3271.56,3841.57 C43.2@3272.57,3840.56 ; U10.12@3271.56,4080.94 3271.56,4113.26 3275.79,4117.5 3275.79,4190.32 C137.2@3277.88,4192.41 C137.2@3277.88,4223.9 ; Y1.4@3623.17,4054.18 3630.08,4054.18 3646.39,4037.87 3650.02,4037.87 v3(3651.36,4036.53) ; v3@3649.9,4034.08 3651.01,4035.19 3656.94,4035.19 3672.19,4019.94 Y1.2@3672.19,4013.38 ; C90.2@3697.69,4182.85 3698.99,4181.54 3698.99,4160.07 v1(3700.3,4158.76) ; v1(3710.74,4233.04) 3712.91,4233.04 3717.38,4237.51 3774.43,4237.51 U2.A13@3788.76,4251.85 ; C14.1@3724.34,3990.34 3725.45,3989.23 v1(3738.48,3989.23) 3741.28,3989.23 3741.28,3978.28 3735.46,3972.46 v1(3703.21,3972.46) v1(3680.37,3972.46) v1(3655,3972.46) 3619.79,3972.46 3557.61,4034.64 3557.61,4067.72 3582.02,4092.12 3582.59,4092.12 3592.99,4102.51 3610.06,4102.51 3612.18,4104.63 3614.01,4102.8 3634.43,4102.8 3637.95,4106.32 v1(3639.78,4106.32) 3657.3,4088.8 3668.8,4088.8 3669,4089 3710.92,4089 3722.86,4077.06 3722.86,4076.27 3723.31,4075.82 3735.12,4075.82 3753.66,4094.37 U2.A8@3788.76,4094.37 v1(3804.51,4110.11) ; v1(3733.48,4289.01) 3734.08,4289.6 3734.08,4311.36 C69.2@3734.67,4311.95 ; v1(3767.6,3868.71) 3769.77,3868.71 3773.85,3872.79 3787.66,3872.79 U2.A1@3788.76,3873.89 ; v1(3767.62,3893.2) 3769.15,3894.73 3776.55,3894.73 3787.21,3905.39 U2.A2@3788.76,3905.39 ; v1(3773.02,4393.58) U2.A17@3788.76,4377.83 v1(3804.51,4393.58) ; U2.A6@3788.76,4031.37 v1(3804.51,4047.12) U2.B6@3820.26,4031.37 ; U2.A11@3788.76,4188.85 v1(3804.51,4204.6) U2.B11@3820.26,4188.85 ; U2.A15@3788.76,4314.84 3789.05,4314.84 3803.06,4328.84 v1(3803.35,4328.84) ; U2.A18@3788.76,4409.33 v1(3804.51,4393.58) ; v1@3803.1,4329.14 3804.5,4329.14 3818.81,4314.84 U2.B15@3820.26,4314.84 ; v1@3803.36,4329.14 3819.62,4345.4 U2.B16@3819.62,4346.33 ; v1(3804.51,4173.11) U2.B10@3820.26,4157.36 ; U2.B8@3820.26,4094.37 v1(3836.01,4110.11) ; U2.B9@3820.26,4125.86 v1(3836.01,4110.11) ; U2.B14@3820.26,4283.34 3821.28,4283.34 3834.99,4269.63 v1(3836.01,4269.63) ; U2.B17@3820.26,4377.83 v1(3804.51,4393.58) ; U2.B18@3820.26,4409.33 v1(3804.51,4393.58) ; U2.C6@3851.76,4031.37 v1(3836.01,4047.12) U2.C7@3851.76,4062.87 ; U2.C8@3851.76,4094.37 v1(3836.01,4110.11) ; U2.C13@3851.76,4251.85 3836.01,4267.59 U2.C14@3851.76,4283.34 ; U2.C16@3851.76,4346.33 3867.5,4362.08 U2.D17@3883.25,4377.83 ; U2.C17@3851.76,4377.83 3852.26,4377.83 3867,4363.08 v1(3867.5,4363.08) ; U2.D16@3883.25,4346.33 3883.25,4346.83 3899,4362.58 v1(3899,4363.08) ; U2.D18@3883.25,4409.33 v1(3899,4425.07) U2.E18@3914.75,4409.33 ; v1@3899,4362.08 U2.E16@3914.75,4346.33 ; v1(3899,4393.58) U2.E17@3914.75,4377.83 ; U2.E3@3914.75,3936.89 v1(3930.5,3952.63) ; v1(3930.5,3922.56) 3931.21,3922.56 3945.53,3936.89 U2.F3@3946.24,3936.89 ; v1(3930.5,4362.62) 3930.5,4362.35 3946.24,4346.6 U2.F16@3946.24,4346.33 ; v1(3930.5,4425.07) U2.F18@3946.24,4409.33 v1(3930.5,4393.58) U2.F17@3946.24,4377.83 ; U2.K16@4072.23,4346.33 4072.23,4346.52 4087.98,4362.27 v1(4087.98,4362.45) ; U2.K17@4072.23,4377.83 v1(4087.98,4393.58) ; U2.K18@4072.23,4409.33 v1(4087.98,4393.58) ; v1@4087.98,4362.08 U2.L16@4103.72,4346.33 ; v1(4087.98,4425.07) U2.L18@4103.72,4409.33 ; U2.L17@4103.72,4377.83 v1(4087.98,4393.58) ; v1(4119.47,4393.58) U2.L18@4103.72,4409.33 ; U2.N3@4166.72,3936.89 v1(4182.46,3921.14) U2.P3@4198.21,3936.89 ; U2.N16@4166.72,4346.33 4166.72,4346.77 4182.46,4362.51 v1(4182.46,4362.94) ; U2.N17@4166.72,4377.83 v1(4182.46,4393.58) U2.N18@4166.72,4409.33 v1(4182.46,4425.07) ; v1@4182.46,4362.08 U2.P16@4198.21,4346.33 ; v1(4213.96,3952.63) U2.R3@4229.71,3936.89 ; U2.R16@4229.71,4346.33 4229.71,4346.83 4245.46,4362.58 v1(4245.46,4363.08) ; U2.R17@4229.71,4377.83 4229.71,4378.23 4245.46,4393.98 v1(4245.46,4394.38) ; v1(4245.46,4015.63) U2.T6@4261.2,4031.37 ; v1(4245.46,4299.09) U2.T15@4261.2,4314.84 ; v1@4245.46,4362.08 U2.T16@4261.2,4346.33 ; v1@4245.46,4393.58 U2.T17@4261.2,4377.83 ; U2.T4@4261.2,3968.38 v1(4276.95,3984.13) U2.T5@4261.2,3999.88 ; U2.T7@4261.2,4062.87 v1(4245.46,4078.62) U2.T8@4261.2,4094.37 ; U2.T9@4261.2,4125.86 v1(4245.46,4141.61) U2.T10@4261.2,4157.36 ; U2.T11@4261.2,4188.85 v1(4245.46,4204.6) U2.T12@4261.2,4220.35 ; U2.T13@4261.2,4251.85 v1(4245.46,4267.59) U2.T14@4261.2,4283.34 ; v1(4276.95,4363.08) 4277.45,4363.08 4292.2,4377.83 U2.U17@4292.7,4377.83 ; U2.U1@4292.7,3873.89 v1(4308.45,3858.15) U2.V1@4324.2,3873.89 v1(4339.94,3858.15) 4342.43,3860.63 C60.2@4378.33,3860.63 ; U2.U18@4292.7,4409.33 v1(4308.45,4425.07) ; U2.V17@4324.2,4377.83 v1(4339.94,4393.58) U2.V18@4324.2,4409.33 v1(4339.94,4425.07) ; C96.2@4388.37,4246.78 4388.37,4252.87 v1(4402.94,4267.44) 4388.37,4282.01 C98.2@4388.37,4286.73 ; C102.2@4405.36,4090.24 4405.93,4090.82 C88.2@4405.93,4124.76 4409.76,4124.76 v1@4420.4,4135.4 ; v1(4419.8,4136) 4421.96,4136 4430.03,4144.07 4448.46,4144.07 C18.1@4453.3,4148.91 ; v1(4087.98,4393.58) U2.L18@4103.72,4409.33
  Top Layer w12: v1(4701.87,3656.11) 4702.55,3656.8 4743.74,3656.8 U6.2@4744.43,3657.48
  Top Layer w15: 3272.37,3663.53 3272.37,3808.87 C43.2@3272.57,3809.07 C43.2@3272.57,3840.56 ; v1(3526.1,4502.59) 3527.26,4501.43 3527.26,4478.76 3534.93,4471.1 Q2.2@3538.2,4471.1
  Bottom Layer w5.5: v1(3930.5,4362.62) 3932.47,4360.65 3932.47,4349.93 3932.68,4349.72 3932.89,4349.72 C74.2@3936.37,4346.23 ; C130.2@4241.68,4228 4243.57,4226.11 4243.57,4206.49 v1(4245.46,4204.6) 4257.65,4192.4 4257.65,4187.6 C61.2@4259.95,4185.3
  Bottom Layer w8: R65.1@2451.72,4048.48 2451.83,4048.37 2472.61,4048.37 v1(2472.73,4048.25) 2518.43,4002.55 v1(2518.43,3935.91) ; v1(2651.06,3820.45) 2652.97,3818.54 2652.97,3813.87 2680.91,3785.94 C118.1@2680.91,3780 ; v1@2740.71,4228.58 2751.54,4217.75 2751.54,4166.04 v1(2762.37,4155.21) 2762.37,4116.18 C128.1@2751.38,4105.2 ; C127.1@2844.07,3780.99 2845.95,3782.86 v1(2892.72,3782.86) ; R97.1@3470.06,4016.69 3470.06,4014.72 3483.16,4001.63 3487.99,4001.63 v1(3489.9,3999.72) ; TP15.1@3488.75,4502.59 v1(3526.1,4502.59) R98.2@3526.1,4474.39 R93.2@3526.1,4457.3 R96.2@3526.1,4440.29 ; R119.1@3521.57,4100.58 3522.36,4100.58 3524.66,4102.88 3524.66,4106.45 3535.73,4117.52 3567.16,4117.52 3580.13,4104.55 3611.09,4104.55 v1(3611.59,4104.04) ; C59.2@4146.24,3989.57 4146.24,4013.66 4156.48,4023.9 v1(4156.48,4026.61) ; v1(5229.76,4068.4) 5229.76,4134.14 v1(5259.14,4163.53)
  Bottom Layer w10: U9.4@3625.17,3964.2 3646.74,3964.2 v1(3655,3972.46) ; C101.2@3751.01,3881.17 3751.01,3861.79 C100.2@3751.11,3861.69 3753.05,3861.69 3758.54,3867.18 3766.07,3867.18 v1(3767.6,3868.71) ; v1(3767.62,3893.2) 3769.15,3894.73 3772.69,3894.73 3789.82,3911.86 3791.12,3911.86 R3.2@3791.48,3912.22 ; C97.2@3779.79,4061.22 3790.41,4061.22 v1(3804.51,4047.12) ; C67.2@3853,4338.02 3874.98,4338.02 3877,4336 C73.2@3877,4303 ; v1(3867.5,4363.08) 3867.5,4347.58 3876,4339.08 3899,4362.08 v1(3899,4363.08) ; C68.2@3895.39,4409.24 3895.39,4421.47 v1(3899,4425.07) ; C64.2@3918.02,4159 3936,4159 3953.61,4176.61 3942.22,4188 C65.2@3931,4188 ; C66.2@3919.05,4218 3955.09,4218 v1(3956.48,4216.61) ; C95.2@3922.37,3902.78 3922.37,3913.01 3930.5,3921.14 v1(3930.5,3922.56) ; C62.2@3927,4128 3947.87,4128 v1(3956.48,4136.61) ; C75.2@3934.43,4409.11 3934.35,4409.02 3934.35,4397.43 v1(3930.5,4393.58) 3936.37,4387.7 C76.2@3936.37,4377.73 ; C84.2@4020.26,4377.83 4020.26,4388.85 v1(4024.98,4393.58) 4020.26,4398.3 C85.2@4020.26,4409.33 ; C87.2@4031,3861.38 4031.79,3861.38 4044.6,3874.19 4044.6,3887.25 4050.46,3893.11 C92.2@4065.74,3893.11 4065.74,3891.31 4065.91,3891.14 4082.89,3891.14 4085.81,3888.21 v1(4087.98,3888.21) ; C80.2@4083.77,4377.76 4085.14,4377.76 4086.45,4376.45 4086.45,4363.98 v1(4087.98,4362.45) ; C81.2@4084.39,4409.24 4084.39,4397.16 v1(4087.98,4393.58) ; R170.1@4165.37,3946.46 4182.46,3929.37 v1(4182.46,3921.14) ; C57.2@4177.74,4409.33 4177.74,4398.3 v1(4182.46,4393.58) 4177.39,4388.51 C56.2@4177.39,4378.24 4178.18,4378.24 4179.48,4376.94 4179.48,4368.09 4182.46,4365.11 v1(4182.46,4362.94) ; C57.2@4179.44,4409.4 4179.66,4409.4 4180.95,4410.7 v1@4180.95,4423.56 ; v1(4245.46,4015.63) 4265,4035.17 C91.2@4282.98,4035.17 ; v1@4245.46,4079.47 v1(4245.46,4078.62) 4265.27,4058.8 C103.2@4280.95,4058.8 ; v1(4276.95,3984.13) 4282.16,3978.92 C94.2@4282.16,3964.68 ; R172.1@4401.11,4131.01 4413.91,4131.01 v1@4421,4138.1 ; v1@4421,4136 v1@4421,4138.1 ; v1@4422.04,4139.14 v1@4421,4138.1
  Bottom Layer w15: C85.2@4020.26,4409.33 4020.26,4420.35 v1(4024.98,4425.07)
  other v1: 2925.05,3614.04 2955.47,3613.89 3012.76,3614.46 2875.44,3615.03 2985.47,3614.89 2899.61,3615.6 2848.57,3616.59 3254.23,3617.46 3280.46,3617.21 3307.45,3618.46 3226.5,3618.84 3198.12,3621.63 3040.48,3623.7 3334.16,3624.8 2849.57,3641.9 3227.5,3644.47 3252.26,3644.3 3318.15,3647.37 3294.76,3647.71 3040.06,3654.55 3550.68,3659.15 2848.57,3668.48 3227.5,3670.42 3251.23,3670.24 3294.59,3674.68 3316.27,3674.51 3039.92,3683.84 3551.8,3686.76 3579.59,3688.06 2846.87,3692.08 3226.82,3698.24 3250.21,3698.24 3294.25,3700.12 3316.27,3700.12 3038.64,3711.84 2846.15,3717.1 3225.97,3724.7 3249.7,3724.7 3293.23,3726.23 3316.27,3726.06 2991.44,3736.86 3016.03,3736.72 2863.92,3738.71 3294.59,3750.13 3316.44,3750.13 3225.11,3751.5 3248.67,3751.16 3615.65,3754.48 3567.99,3754.67 4813.98,3792.76 3572.9,3808.68 2568.65,3819.69 2594.93,3819.69 2619.79,3819.69 2518.43,3820.87 2542.05,3820.87 2518.43,3848.42 3478.49,3848.89 3458.47,3861.6 3529.02,3872.82 2518.43,3878.21 3367.38,3879.29 3168.63,3891.88 3190.62,3893.93 3157.12,3908.63 2518.43,3909.71 3176.95,3909.77 3410.21,3920.42 2568.65,3934.73 2594.93,3934.73 2619.79,3934.73 2651.06,3935.49 2682.64,3934.73 2542.05,3935.91 3956.48,4026.61 4006.48,4026.61 4056.48,4026.61 4106.48,4026.61 3956.48,4066.61 4006.48,4066.61 4056.48,4066.61 4106.48,4066.61 4156.48,4066.61 3956.48,4101.61 4006.48,4101.61 4056.48,4101.61 4106.48,4101.59 4156.48,4101.59 3682.73,4109.74 3707.43,4109.58 3667.04,4129.68 4006.48,4136.61 4056.48,4136.61 4106.48,4136.61 4156.48,4136.61 3290.65,4156.46 3667.82,4156.14 3300.24,4175.59 3956.48,4176.61 4006.48,4176.61 4056.48,4176.61 4106.48,4176.61 4156.48,4176.61 2469.52,4178.61 3669.97,4181.83 2921.14,4197.62 2469.52,4213.06 4006.48,4216.61 4056.48,4216.61 4106.48,4216.61 4156.48,4216.61 2739.77,4228.06 2761.98,4227.77 2784.1,4227.87 2993.92,4234.69 2504.49,4237.33 2540.2,4236.84 2573.46,4236.84 2795.55,4246.48 2751.41,4247.06 2773.62,4246.98 5275.39,4285.82 5311.85,4287.19 3708.01,4311.4 3683.06,4312.93 3720.96,4361.73 3745.36,4362.25 3769.24,4362.42 4024.98,4362.53 3175.1,4385.51 2635.18,4400.16 3090.84,4402.11 2526.41,4403.11 2465.87,4403.67 2496.84,4403.94 3013.89,4403.94 3050.66,4403.94 3118.78,4403.75 2982.07,4405.06 2921.53,4405.62 2952.49,4405.9
  other v2: 5465.42,3942.18 5442.78,3979.58 5488.05,3979.58 5465.42,4016.98
NetC5_1: C5.1 C6.1 R1.2 U4.1 U4.2 | length 170
  Top Layer w8: U4.2@5410.3,3992.37 5410.3,4032 5428.61,4050.31 5428.61,4066.15 C5.1@5430.58,4068.12 5430.58,4103.12 C6.1@5430.26,4103.44 5428.23,4105.47 R1.2@5428.23,4152.95
NetC15_1: C15.1 R20.1 R27.2 U4.5 | length 441.9
  Top Layer w5.5: R27.2@5507.74,3893.28 5507.97,3893.51 R27.2@5509.94,3893.51 ; U4.5@5520.53,3941.19 5520.53,3906.07 5516.8,3902.34 5516.8,3900.37 R27.2@5509.94,3893.51 ; v1(5539.31,3893.51) R27.2@5509.94,3893.51
  Top Layer w8: v1(5298.75,4011.43) 5299.57,4012.25 5332.45,4012.25 C15.1@5333.26,4013.06 5366.72,4013.06 R20.1@5366.79,4013.13
  Sig2 w8: v1(5298.75,4011.43) 5416.68,3893.51 v1(5539.31,3893.51)
NetC21_1: C21.1 R39.1 U5.96 | length 158.3
  Top Layer w8: U5.96@4609.94,4492.02 4609.94,4527.31 4597.22,4540.03 4597.22,4588.79 4608.26,4599.82 4610.23,4599.82 4616.07,4605.67 C21.1@4616.07,4607.64 R39.1@4644.55,4607.64
NetC22_2: C22.2 R68.2 U5.68 | length 131.1
  Top Layer w8: U5.68@5050.88,4492.02 5050.88,4516.78 5070.62,4536.51 5076.64,4536.51 5098.41,4558.28 R68.2@5100.38,4558.28 5101.57,4559.47 5137.85,4559.47 C22.2@5139.05,4560.66
NetC23_2: C23.2 U5.89 Y2.3 | length 169.6
  Top Layer w8: U5.89@4720.17,4492.02 4720.17,4550.16 4725.84,4555.82 C23.2@4725.84,4598.27 4747.03,4598.27 4751.94,4593.36 4751.94,4589.42 4769.59,4571.77 Y2.3@4773.53,4571.77
NetC24_2: C24.2 U5.88 Y2.1 | length 431.1
  Top Layer w8: U5.88@4735.92,4492.02 4735.92,4521.04 4754.96,4540.08 4924.93,4540.08 4951.46,4566.61 4951.46,4643.39 4946.78,4648.07 C24.2@4923.56,4648.07 ; Y2.1@4864.08,4642.64 4869.01,4647.57 C24.2@4923.05,4647.57
NetC25_2: C25.2 C26.2 R89.1 U5.9 U6.1 | length 194.7
  Top Layer w8: R89.1@4704.82,3790.42 4706.39,3791.99 4739.65,3791.99 C26.2@4741.22,3793.56 ; U5.9@4735.92,3885.72 4735.98,3885.66 4735.98,3833.89 C25.2@4741.22,3828.66 C26.2@4741.22,3793.56 ; U6.1@4744.43,3732.29 4741.22,3735.5 C26.2@4741.22,3793.56
NetC49_2: C49.2 U10.18 | length 95.7
  Top Layer w8: C49.2@3100.25,4041.76 3110.28,4031.72 U10.18@3191.83,4031.72
NetC117_1: C117.1 L6.1 U8.13 U8.14 | length 150.7
  Top Layer w8: U8.14@2771.82,4287.63 2771.82,4294.52 2787.99,4310.69 2791.5,4310.69
  Top Layer w10: L6.1@2784.02,4401.99 2791.5,4394.51 C117.1@2791.5,4333.75 2791.5,4310.69 U8.13@2791.5,4287.63
NetC117_2: C117.2 U8.15 | length 46.1
  Top Layer w10: U8.15@2752.13,4287.63 C117.2@2752.13,4333.75
NetC136_1: C136.1 R115.1 U8.20 | length 127.3
  Top Layer w10: v1(2646.13,4214.75) 2647.67,4216.28 2653.32,4216.28 2655.78,4218.74 U8.20@2704.89,4218.74
  Bottom Layer w10: R115.1@2620.02,4172.94 C136.1@2620.02,4213.06 2621.71,4214.75 v1(2646.13,4214.75)
NetD1_2: D1.2 FL2.2 | length 46.2
  Top Layer w15: FL2.2@2374.88,4153.82 2375.57,4153.14 2375.57,4108.84 D1.2@2376.25,4108.15
NetD2_1: D2.1 R104.1 | length 48.2
  Top Layer w8: D2.1@3445.38,4533.92 R104.1@3493.62,4533.92
NetD2_2: D2.2 Q2.3 | length 43.8
  Top Layer w8: Q2.3@3443.71,4433.69 3444.56,4434.55 3444.56,4476.01 D2.2@3445.38,4476.83
NetJ9_1: J9.1 R109.2 | length 1000.9
  Top Layer w5.5: v1(3531.37,3958.79) 3552.91,3958.79 3558.26,3953.43 3742.32,3953.43 v1(3773.02,3984.13) ; R109.2@3743.83,4012.09 3748.95,4006.97 3750.35,4006.97 v1@3773.02,3984.3
  Top Layer w8: J9.1@2946.25,3736.15 2946.25,3737.13 2989.05,3779.93 3046.83,3779.93 v1(3047.85,3780.95)
  Sig2 w4.2: v1(3047.85,3780.95) 3047.85,3764.21 3050.31,3761.75 3159.48,3761.75 3302.35,3904.62 3477.2,3904.62 v1(3531.37,3958.79)
NetL11_1: L11.1 U10.11 | length 156.8
  Top Layer w8: U10.11@3291.24,4087.83 3292.16,4088.75 3292.16,4128.97 3359.76,4196.56 L11.1@3379.44,4196.56
NetLD1_1: LD1.1 R105.2 | length 36.5
  Top Layer w15: R105.2@2358.26,3920.93 2364.22,3914.96 2388.97,3914.96 LD1.1@2391.31,3912.62
NetLD2_1: LD2.1 R13.2 | length 29
  Top Layer w5.5: R13.2@5260.74,3687.65 5260.74,3659.66 LD2.1@5261.45,3658.94
NetLD3_2: LD3.2 R42.1 | length 34.7
  Top Layer w8: LD3.2@4447.13,4276.5 4475.98,4276.5 4479.55,4272.94 R42.1@4479.55,4272.15
NetLD5_1: LD5.1 R107.2 | length 33.1
  Top Layer w5.5: LD5.1@5458.65,4411.13 5462.03,4407.75 R107.2@5490.33,4407.75
NetLD5_2: LD5.2 Q1.3 | length 49.8
  Top Layer w5.5: Q1.3@5412.69,4367.71 5451.56,4367.71 5458.65,4374.8 LD5.2@5458.65,4375.7
NetQ1_1: Q1.1 R108.2 | length 481.2
  Top Layer w5.5: Q1.1@5343.65,4403.73 v1(5343.65,4444.91) ; R108.2@5343.82,4068.68 5344.6,4068.68 5348.15,4065.13 5348.15,4064.49 5351.38,4061.27 5380.08,4061.27 v1(5380.64,4060.71)
  Bottom Layer w5.5: v1(5343.65,4444.91) 5380.64,4407.92 v1(5380.64,4060.71)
